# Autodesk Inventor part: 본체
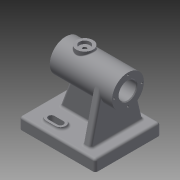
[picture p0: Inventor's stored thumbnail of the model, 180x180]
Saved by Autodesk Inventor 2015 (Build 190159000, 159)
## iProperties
Created: 2022-06
Part Number: 본체
Material: 일반
Document SubType Name: Modeling
Designer: 103-20
Density: 1 g/cm^3
Appearance: 기본값
Author: 103-20
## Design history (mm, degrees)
sketch "스케치1"
  geometry: L1 (0, 0)-(100, 0); L2 (100, 0)-(100, 86); L3 (100, 86)-(0, 86); L4 (0, 86)-(0, 0)
  constraints: 8 end point, 2 parallel, 1 horizontal, 1 perpendicular
  dimensions: "d0" = 100 distance of L2.end L3.end; "d1" = 86 distance of L1.end L2.end
extrude "돌출1" new body sketch "스케치1" distance "d2" = 15; taper "d3" = 0 deg
node "작업 평면1"
sketch "스케치4"
  geometry: L1 (0, 0)-(0, 86) reference; L2 (0, 0)-(-15, 0) reference; L3 (-15, 0)-(-15, 86) reference; L4 (-15, 8)-(-76.814, 22.559); L5 (-15, 78)-(-76.814, 63.441); L6 (0, 0)-(-15, 0) reference; L7 (-15, 0)-(-15, 86) reference; L8 (-15, 86)-(0, 86) reference; L9 (0, 86)-(0, 0) reference; A1 r 21 centre (-72, 43) between (-76.814, 22.559) and (-76.814, 63.441)
  constraints: 4 end point, 2 point on circle, 2 point on line, 2 tangent, 1 centre point
  dimensions: "d12" = 42 diameter of A1; "d13" = 72 distance from line of A1.centre L1; "d14" = 43 distance from line of L2 A1.centre; "d15" = 8 distance of L2.end L4.start; "d16" = 8 distance of L3.end L5.start
extrude "돌출2" join sketch "스케치4" distance "d17" = 10; taper "d18" = 0 deg
sketch "스케치5"
  geometry: L1 (75, 8)-(75, 78) reference; L2 (0, 86)-(0, 0) reference; L3 (75, 48)-(15, 48); L4 (15, 48)-(15, 38); L5 (15, 38)-(75, 38); L6 (75, 38)-(75, 48); L7 (75, 48)-(15, 38); L8 (15, 48)-(75, 38); 3 further points
  constraints: 12 end point, 4 midpoint, 2 parallel, 1 horizontal, 1 perpendicular
  dimensions: "d19" = 43 vertical distance of point (100, 0) point (45, 43); "d20" = 10 distance of L3.end L4.end; "d21" = 15 distance between parallel lines of L2 L4
extrude "돌출3" join sketch "스케치5" distance "d22" = 72; taper "d23" = 0 deg
sketch "스케치6"
  geometry: L1 (0, 0)-(0, 86) reference; L2 (0, 86)-(-15, 86) reference; C1 r 21 at (-72, 43)
  constraints: 1 centre point
  dimensions: "d24" = 42 diameter of C1; "d25" = 43 distance from line of C1.centre L2; "d26" = 72 distance from line of L1 C1.centre
extrude "돌출4" join sketch "스케치6" distance "d27" = 82; taper "d28" = 0 deg
feature "면 기울기1" dims angle "d29" = 20 deg
sketch "스케치7"
  geometry: C1 r 21 at (0, 0) reference; C2 r 11.5 at (0, 0); 1 further point
  constraints: 1 centre point, 1 coincident
  dimensions: "d30" = 23 diameter of C2
extrude "돌출5" cut sketch "스케치7" distance "d31" = 20; taper "d32" = 0 deg
sketch "스케치8"
  geometry: C1 r 21 at (0, 0) reference; C2 r 14.5 at (0, 0); 1 further point
  constraints: 1 centre point, 1 coincident
  dimensions: "d33" = 29 diameter of C2
extrude "돌출6" cut sketch "스케치8" distance "d34" = 62; taper "d35" = 0 deg
sketch "스케치9"
  geometry: C1 r 11.5 at (0, 0) reference; 2 further points
  constraints: 1 horizontal alignment
  dimensions: "d42" = 18 distance of C1.centre point (-18, 0)
hole "구멍1" sketch "스케치9" at (-18, 0) diameter "d43" = 2.459; stored, may be unused: countersink angle "d47" = 90 deg, drill point angle "d49" = 118 deg; dims "d44" = 8, "d45" = 4, "d46" = 2, "d48" = 10
sketch "스케치10"
  geometry: C1 r 14.5 at (0, 0) reference; 2 further points
  constraints: 1 horizontal alignment
  dimensions: "d53" = 18 distance of C1.centre point (18, 0)
hole "구멍2" sketch "스케치10" at (18, 0) diameter "d54" = 2.459; stored, may be unused: countersink angle "d58" = 90 deg, drill point angle "d60" = 118 deg; dims "d55" = 8, "d56" = 4, "d57" = 2, "d59" = 10
node "작업 평면2"
sketch "스케치11"
  geometry: L1 (18, 64)-(18, 22) reference; C1 r 11 at (43, 43); 2 further points
  constraints: 1 centre point, 1 horizontal alignment, 1 midpoint
  dimensions: "d65" = 22 diameter of C1; "d66" = 25 distance from line of L1 C1.centre
extrude "돌출7" join sketch "스케치11" stored distance "d67" = 62; taper "d68" = 0 deg
sketch "스케치12"
  geometry: C1 r 11 at (0, 0) reference; 1 further point
hole "구멍3" sketch "스케치12" at (0, 0) diameter "d69" = 4.917; stored, may be unused: countersink angle "d73" = 90 deg, drill point angle "d75" = 0 deg; dims "d70" = 12, "d71" = 14, "d72" = 4, "d74" = 17.1
fillet "모깎기7" dims "d76" = 1
chamfer "모따기1" distance "d77" = 1; stored, may be unused: second distance "d78" = 2, angle "d79" = 45 deg
sketch "스케치14"
  geometry: L1 (0, 0)-(100, 0) reference; L2 (100, 86)-(0, 86) reference; L3 (0, 86)-(0, 0) reference; L4 (26, 70)-(38, 70); L5 (26, 63)-(38, 63); L6 (38, 77)-(26, 77); L7 (26, 16)-(38, 16); L8 (26, 9)-(38, 9); L9 (38, 23)-(26, 23); A1 r 7 centre (26, 70) between (26, 77) and (26, 63); A2 r 7 centre (38, 70) between (38, 63) and (38, 77); A3 r 7 centre (26, 16) between (26, 23) and (26, 9); A4 r 7 centre (38, 16) between (38, 9) and (38, 23); 2 further points
  constraints: 16 end point, 8 point on circle, 8 tangent, 4 centre point, 3 parallel, 2 midpoint, 1 horizontal
  dimensions: "d83" = 16 distance from line of L1 L7.start; "d84" = 54 distance of L4.start L7.start; "d85" = 12 distance of L4.end L4.start; "d86" = 12 distance of L7.end L7.start; "d87" = 16 distance from line of L2 L4.start; "d88" = 26 distance from line of L3 L4.start; "d92" = 14 distance between parallel lines of L5 L6; "d93" = 14 distance between parallel lines of L8 L9
fillet "모깎기8" dims "d89" = 3
fillet "모깎기9" dims "d90" = 3
fillet "모깎기10" dims "d91" = 3
extrude "돌출8" join sketch "스케치14" distance "d94" = 3; taper "d95" = 0 deg
sketch "스케치15"
  geometry: L1 (26, 70)-(38, 70); L2 (26, 66)-(38, 66); L3 (38, 74)-(26, 74); A1 r 7 centre (38, 70) between (38, 63) and (38, 77) reference; A2 r 7 centre (26, 70) between (26, 77) and (26, 63) reference; A3 r 4 centre (26, 70) between (26, 74) and (26, 66); A4 r 4 centre (38, 70) between (38, 66) and (38, 74); 2 further points
  constraints: 8 end point, 4 point on circle, 4 tangent, 2 centre point, 1 horizontal, 1 midpoint, 1 parallel
  dimensions: "d96" = 8 distance between parallel lines of L2 L3
extrude "돌출9" cut sketch "스케치15" stored distance "d97" = 3; taper "d98" = 0 deg
node "작업 평면3"
fillet "모깎기11" dims "d99" = 3
fillet "모깎기12" dims "d100" = 3
fillet "모깎기13" dims "d101" = 3
fillet "모깎기14" dims "d102" = 3
node "솔리드1"
pattern_circular "원형 패턴1" dims angle "d51" = 360 deg
pattern_circular "원형 패턴2" dims angle "d62" = 360 deg
mirror "대칭1"
node "절단 모서리 투영1"
other parameters: "d11" = -15, "d64" = 96
